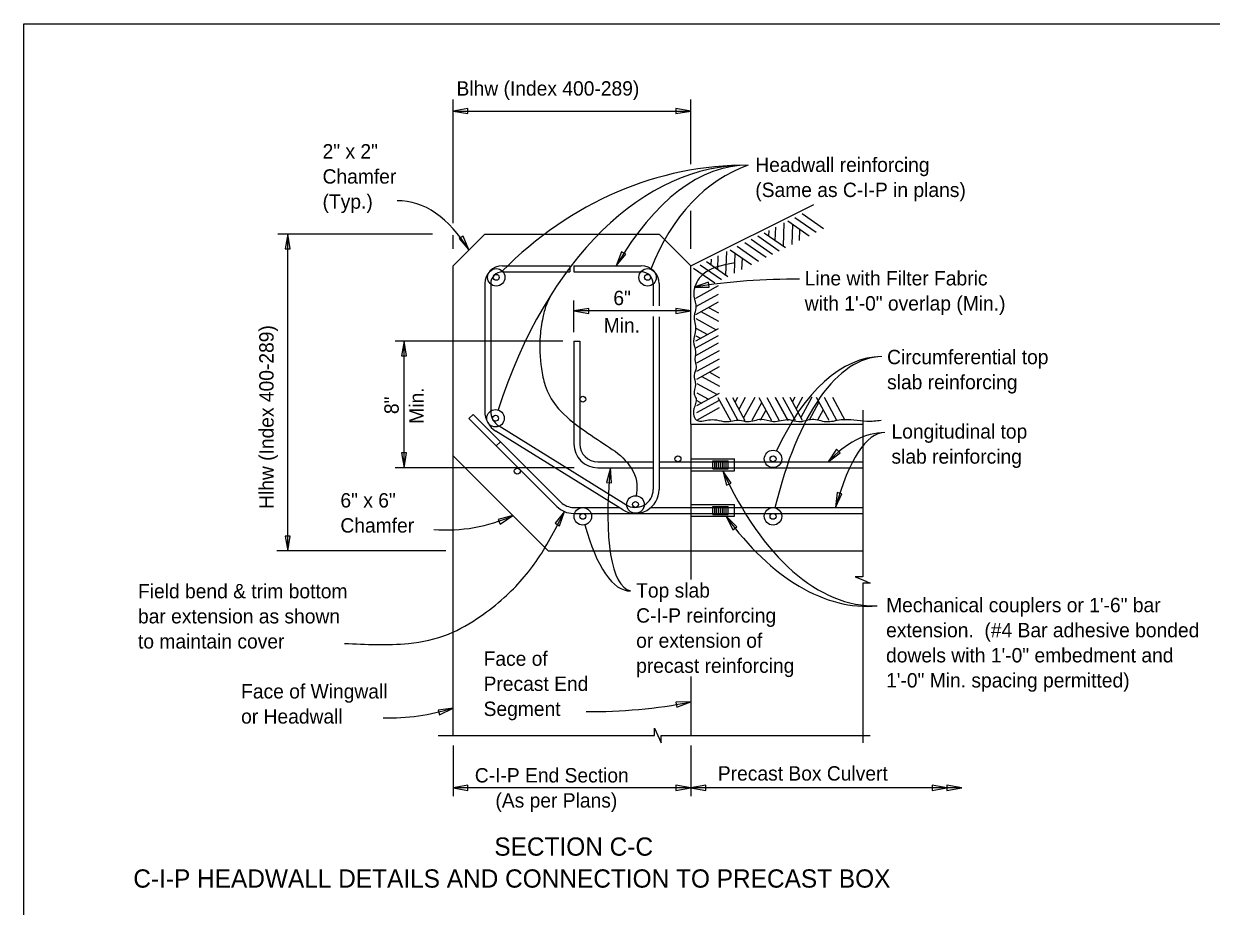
# Model space of a CAD drawing. Extents: x 0 to 15.4, y 0 to 9.7.
# Drawn here: x 0 to 6.24, y 5.1 to 9.74 of the extents above; entities that cross this region are included whole.
import ezdxf

# ---------------------------------------------------------------- set-up
doc = ezdxf.new("R2010")
doc.units = 0
for name, color, linetype in [('Dimension', 7, 'Continuous'), ('Miscellaneous', 7, 'Continuous'), ('Miscellaneous1', 7, 'Continuous'), ('Rebar', 7, 'Continuous'), ('SubStrConc', 7, 'Continuous'), ('TextStructures', 7, 'Continuous')]:
    doc.layers.add(name, color=color, linetype=linetype)

msp = doc.modelspace()

# ---------------------------------------------------------------- linework, layer by layer
at = {"layer": 'Dimension'}
for p, q in [((2.2567, 8.6893), (2.2567, 9.3394)), ((3.5067, 9), (3.5067, 9.3394)), ((2.2567, 9.2789), (3.5067, 9.2789)), ((3.5067, 8.5545), (3.5067, 8.7544)), ((2.1482, 8.6319), (1.3355, 8.6319)), ((1.3881, 6.9652), (1.3881, 8.6319)), ((2.2567, 8.5545), (2.2567, 8.6268)), ((2.8922, 8.1171), (2.8922, 8.2828)), ((3.5067, 8.2279), (2.8922, 8.2279)), ((2.8342, 8.0695), (1.953, 8.0695)), ((1.9994, 7.4028), (1.9994, 8.0695)), ((2.8933, 7.4028), (1.953, 7.4028)), ((2.2191, 6.9652), (1.3309, 6.9652)), ((2.2567, 5.9412), (2.2567, 5.6754)), ((3.5067, 5.9412), (3.5067, 5.6754)), ((3.5067, 5.7192), (2.2567, 5.7192)), ((4.931, 5.7192), (3.5067, 5.7192))]:
    msp.add_line(p, q, dxfattribs=at)
for points in [[(2.2567, 9.2789), (2.3348, 9.2657), (2.3348, 9.2921)], [(3.5067, 9.2789), (3.4286, 9.2921), (3.4286, 9.2657)], [(1.3881, 8.6319), (1.3748, 8.5538), (1.4013, 8.5538)], [(2.3401, 8.5486), (2.3107, 8.6221), (2.2881, 8.6083)], [(3.1144, 8.4652), (3.1649, 8.5263), (3.142, 8.5395)], [(3.5242, 8.3537), (3.6034, 8.3529), (3.5992, 8.379)], [(2.8922, 8.2279), (2.9703, 8.2147), (2.9703, 8.2412)], [(3.5067, 8.2279), (3.4286, 8.2412), (3.4286, 8.2147)], [(1.9993, 8.0695), (1.9861, 7.9914), (2.0126, 7.9914)], [(4.2289, 7.434), (4.2918, 7.4822), (4.2724, 7.5002)], [(1.9993, 7.4028), (2.0126, 7.4809), (1.9861, 7.4809)], [(3.0838, 7.4028), (3.0632, 7.3263), (3.0895, 7.3238)], [(3.6744, 7.3874), (3.6946, 7.3108), (3.7187, 7.3217)], [(4.2677, 7.1943), (4.3013, 7.266), (4.2758, 7.2731)], [(2.5709, 7.151), (2.4943, 7.131), (2.5051, 7.1069)], [(2.8426, 7.1726), (2.7928, 7.111), (2.8159, 7.0981)], [(3.6918, 7.1477), (3.727, 7.0767), (3.7484, 7.0923)], [(1.3881, 6.9652), (1.4013, 7.0433), (1.3748, 7.0433)], [(2.2567, 6.1391), (2.1782, 6.1282), (2.1862, 6.1029)], [(3.5067, 6.1713), (3.4275, 6.1691), (3.4326, 6.1431)], [(2.2567, 5.7192), (2.3348, 5.706), (2.3348, 5.7325)], [(3.5067, 5.7192), (3.4286, 5.7325), (3.4286, 5.706)], [(3.5067, 5.7192), (3.5848, 5.706), (3.5848, 5.7325)], [(4.853, 5.7192), (4.7749, 5.7325), (4.7749, 5.706)], [(4.931, 5.7192), (4.853, 5.7325), (4.853, 5.706)]]:
    msp.add_lwpolyline(points, close=True, dxfattribs=at)
for points in [[(4.4103, 7.7058), (4.4103, 6.83), (4.3715, 6.83), (4.4103, 6.8132), (4.449, 6.7963), (4.4103, 6.7963), (4.4103, 5.9557)], [(2.1788, 5.9944), (3.3166, 5.9944), (3.3166, 6.0332), (3.3335, 5.9944), (3.3504, 5.9557), (3.3504, 5.9944), (4.449, 5.9944)]]:
    msp.add_lwpolyline(points, dxfattribs=at)
for centre in [(2.4839, 8.4047), (3.2795, 8.4047), (2.4801, 7.6634), (3.939, 7.4496), (3.2159, 7.2099), (2.939, 7.1475), (3.939, 7.1475)]:
    msp.add_circle(centre, 0.0459, dxfattribs=at)
for centre, radius, start, end in [((4.0438, 5.0922), 3.3027, 89.39705, 99.05348), ((2.22, 7.93), 0.8544, 265.64331, 294.25209), ((1.9186, 7.2073), 1.1204, 268.54133, 287.56513), ((2.9908, 8.7724), 2.6517, 269.25675, 281.21871)]:
    msp.add_arc(centre, radius, start, end, dxfattribs=at)
for centre, major_axis, ratio, start_param, end_param in [((3.7845, 6.6328), (-0.0243, -2.3612), 0.617071, 3.141593, 4.246347), ((3.7916, 6.7521), (-0.0172, -2.2419), 0.865159, 3.141593, 3.868244), ((3.7834, 6.5654), (-0.0255, -2.4287), 0.452522, 3.141593, 3.818879), ((4.4723, 7.0644), (0.6635, -1.9296), 0.580134, 3.141593, 3.735964), ((1.984, 7.8602), (0.0202, -0.9471), 0.562458, 2.372304, 3.141593), ((4.5275, 6.3273), (0.0171, -1.6604), 0.402699, 3.141593, 4.160334), ((4.5275, 6.3273), (0.0171, -1.6604), 0.473544, 3.141593, 3.930463), ((4.5609, 5.8713), (0.0343, -1.7172), 0.430483, 3.141593, 3.560489), ((4.5609, 5.8713), (0.0343, -1.7172), 0.245056, 3.141593, 3.827956), ((3.4878, 7.9782), (0.2985, 1.223), 0.238216, 2.117736, 3.141593), ((4.4472, 8.7163), (-0.0394, 2.0403), 0.511198, 2.270212, 3.141593), ((4.2975, 8.9171), (-0.1891, 2.2412), 0.515902, 2.436127, 3.141593), ((3.1606, 7.5661), (-0.0288, 0.811), 0.337532, 2.166568, 3.141593)]:
    msp.add_ellipse(centre, major_axis=major_axis, ratio=ratio, start_param=start_param, end_param=end_param, dxfattribs=at)
for points in [[(2.7746, 8.3181), (2.7462, 8.2574), (2.7287, 8.1933), (2.7147, 8.0965), (2.7218, 7.9244), (2.7407, 7.8365), (2.7993, 7.7279), (2.9165, 7.6209), (3.0493, 7.5297), (3.1624, 7.4418), (3.2233, 7.316), (3.2191, 7.2557)], [(1.6858, 6.4793), (2.0233, 6.4793), (2.2331, 6.5283), (2.3999, 6.6212), (2.5253, 6.7198), (2.7032, 6.9244), (2.8426, 7.1726)]]:
    msp.add_spline(points, degree=3, dxfattribs=at)
at = {"layer": 'Miscellaneous'}
for p, q in [((3.5067, 8.4652), (4.1533, 8.7885)), ((4.0929, 8.7397), (4.2051, 8.6619)), ((3.9963, 8.6914), (3.9917, 8.5695)), ((4.0161, 8.7013), (4.1287, 8.6237)), ((4.041, 8.6842), (4.0373, 8.578)), ((4.0533, 8.7199), (4.1655, 8.6421)), ((3.8585, 8.6225), (3.9707, 8.5447)), ((3.8915, 8.639), (4.0037, 8.5612)), ((3.916, 8.6513), (3.915, 8.6228)), ((3.9518, 8.6692), (3.9492, 8.599)), ((4.0788, 8.6581), (4.0765, 8.5976)), ((3.7505, 8.5683), (3.8628, 8.4905)), ((3.7902, 8.5882), (3.9024, 8.5103)), ((3.8234, 8.605), (3.9356, 8.5271)), ((3.6132, 8.4997), (3.6122, 8.4712)), ((3.649, 8.5176), (3.6465, 8.4474)), ((3.6936, 8.5399), (3.689, 8.418)), ((3.7134, 8.5498), (3.8259, 8.4721)), ((3.7383, 8.5326), (3.7346, 8.4264)), ((3.7761, 8.5065), (3.7738, 8.446)), ((3.5207, 8.4534), (3.6329, 8.3756)), ((3.5558, 8.4709), (3.668, 8.3931)), ((3.5888, 8.4875), (3.701, 8.4096)), ((3.5323, 8.2955), (3.6521, 8.3611)), ((3.5323, 8.2512), (3.6521, 8.3168)), ((3.5323, 8.2097), (3.6521, 8.2756)), ((3.599, 8.2464), (3.6521, 8.2174)), ((3.5323, 8.1876), (3.6392, 8.1289)), ((3.5588, 8.2243), (3.6521, 8.1735)), ((3.5323, 8.1377), (3.5939, 8.1041)), ((3.5323, 8.0704), (3.6521, 8.1359)), ((3.5323, 8.0335), (3.6521, 8.099)), ((3.5323, 8.0977), (3.5573, 8.0841)), ((3.5323, 7.9943), (3.6521, 8.0598)), ((3.5376, 7.9549), (3.6574, 8.0205)), ((3.5376, 7.9106), (3.6574, 7.9762)), ((3.5376, 7.8691), (3.6574, 7.935)), ((3.5641, 7.8837), (3.6574, 7.8328)), ((3.6043, 7.9058), (3.6574, 7.8767)), ((3.5376, 7.8469), (3.6445, 7.7883)), ((3.5376, 7.7971), (3.5992, 7.7635)), ((3.5376, 7.7298), (3.6574, 7.7953)), ((3.5376, 7.6928), (3.6574, 7.7584)), ((3.5376, 7.7571), (3.5626, 7.7434)), ((3.6491, 7.7719), (3.7146, 7.6521)), ((3.6882, 7.7719), (3.7538, 7.6521)), ((3.7252, 7.7719), (3.7907, 7.6521)), ((3.7525, 7.7719), (3.7389, 7.7468)), ((3.7925, 7.7719), (3.7589, 7.7102)), ((3.8424, 7.7719), (3.7837, 7.6649)), ((3.8791, 7.7454), (3.8282, 7.6521)), ((3.8645, 7.7719), (3.9304, 7.6521)), ((3.906, 7.7719), (3.9716, 7.6521)), ((3.9503, 7.7719), (4.0159, 7.6521)), ((3.9504, 7.7739), (4.0159, 7.6541)), ((3.9895, 7.7739), (4.0551, 7.6541)), ((4.0265, 7.7739), (4.092, 7.6541)), ((4.0538, 7.7739), (4.0402, 7.7489)), ((4.0938, 7.7739), (4.0602, 7.7122)), ((4.1437, 7.7739), (4.085, 7.6669)), ((4.1804, 7.7474), (4.1296, 7.6541)), ((4.1658, 7.7739), (4.2317, 7.6541)), ((4.2073, 7.7739), (4.2729, 7.6541)), ((4.2516, 7.7739), (4.3172, 7.6541)), ((3.5376, 7.6536), (3.6574, 7.7192)), ((3.9012, 7.7051), (3.8721, 7.6521)), ((4.2025, 7.7072), (4.1735, 7.6541)), ((3.5067, 7.4494), (3.7355, 7.4494)), ((3.6226, 7.4393), (3.6626, 7.4393)), ((3.6226, 7.3975), (3.6226, 7.4393)), ((3.6326, 7.3975), (3.6326, 7.4393)), ((3.6426, 7.3975), (3.6426, 7.4393)), ((3.6526, 7.3975), (3.6526, 7.4393)), ((3.6626, 7.4393), (3.7026, 7.4393)), ((3.6626, 7.3975), (3.6626, 7.4393)), ((3.6726, 7.3975), (3.6726, 7.4393)), ((3.6826, 7.3975), (3.6826, 7.4393)), ((3.6926, 7.3975), (3.6926, 7.4393)), ((3.7026, 7.3975), (3.7026, 7.4393)), ((3.5067, 7.3874), (3.7355, 7.3874)), ((3.6226, 7.3975), (3.6626, 7.3975)), ((3.6626, 7.3975), (3.7026, 7.3975)), ((3.5067, 7.2097), (3.7355, 7.2097)), ((3.6226, 7.1996), (3.7026, 7.1996)), ((3.6226, 7.1578), (3.6226, 7.1996)), ((3.6326, 7.1578), (3.6326, 7.1996)), ((3.6426, 7.1578), (3.6426, 7.1996)), ((3.6526, 7.1578), (3.6526, 7.1996)), ((3.6626, 7.1578), (3.6626, 7.1996)), ((3.6726, 7.1578), (3.6726, 7.1996)), ((3.6826, 7.1578), (3.6826, 7.1996)), ((3.6926, 7.1578), (3.6926, 7.1996)), ((3.7026, 7.1578), (3.7026, 7.1996)), ((3.5067, 7.1477), (3.7355, 7.1477)), ((3.6226, 7.1578), (3.7026, 7.1578))]:
    msp.add_line(p, q, dxfattribs=at)
for points in [[(3.7355, 7.3874), (3.7355, 7.4494)], [(3.7355, 7.1477), (3.7355, 7.2097)]]:
    msp.add_lwpolyline(points, dxfattribs=at)
msp.add_spline([(3.7394, 8.4816), (3.5514, 8.4001), (3.5228, 8.3048), (3.533, 8.245), (3.5241, 8.2018), (3.5317, 8.1305), (3.5215, 8.0669), (3.5317, 8.0135), (3.5291, 7.9613), (3.5355, 7.9295), (3.5241, 7.8901), (3.5317, 7.8405), (3.5241, 7.7909), (3.5342, 7.7667), (3.5228, 7.7132), (3.5412, 7.6511), (3.5649, 7.6489), (3.5991, 7.6547), (3.6411, 7.6547), (3.6907, 7.6458), (3.7632, 7.6535), (3.8052, 7.6458), (3.8765, 7.6585), (3.9401, 7.6471), (4.024, 7.656), (4.0737, 7.6458), (4.1449, 7.6585), (4.2174, 7.6458), (4.2963, 7.656), (4.432, 7.6484), (4.5067, 7.6527)], degree=3, dxfattribs=at)
at = {"layer": 'Miscellaneous1'}
msp.add_lwpolyline([(0, 9.7387), (15.4, 9.7387), (15.4, 0), (0, 0)], close=True, dxfattribs=at)
at = {"layer": 'Rebar'}
for p, q in [((2.5171, 8.4652), (2.8713, 8.4652)), ((2.5171, 8.434), (2.8713, 8.434)), ((2.8713, 8.4652), (2.8713, 8.434)), ((2.8921, 8.4652), (2.8921, 8.434)), ((2.8921, 8.4652), (3.2463, 8.4652)), ((2.8921, 8.434), (3.2463, 8.434)), ((2.4234, 8.3715), (2.4234, 7.7015)), ((2.4546, 8.3715), (2.4546, 7.7015)), ((3.3088, 8.3715), (3.3088, 8.2542)), ((3.34, 8.3715), (3.34, 8.2542)), ((3.3088, 8.1983), (3.3088, 7.2881)), ((3.34, 8.1976), (3.34, 7.2881)), ((2.8922, 8.0695), (2.8922, 7.5278)), ((2.8922, 8.0695), (2.9234, 8.0695)), ((2.9234, 8.0695), (2.9234, 7.5278)), ((2.34, 7.6618), (2.3621, 7.6838)), ((2.5061, 7.5398), (2.3621, 7.6838)), ((2.484, 7.5177), (2.34, 7.6618)), ((3.1656, 7.2084), (2.499, 7.6218)), ((3.1491, 7.1819), (2.4825, 7.5952)), ((2.484, 7.5177), (2.5061, 7.5398)), ((2.8021, 7.1997), (2.484, 7.5177)), ((2.8241, 7.2218), (2.5061, 7.5398)), ((3.0172, 7.434), (3.3088, 7.434)), ((3.34, 7.434), (4.4103, 7.434)), ((3.0172, 7.4028), (3.3088, 7.4028)), ((3.34, 7.4028), (4.4103, 7.4028)), ((3.3575, 7.4028), (3.5276, 7.4028)), ((2.8904, 7.1943), (3.1291, 7.1943)), ((3.2976, 7.1943), (4.4103, 7.1943)), ((2.8904, 7.1631), (4.4103, 7.1631))]:
    msp.add_line(p, q, dxfattribs=at)
for centre in [(2.4839, 8.4047), (3.2795, 8.4047), (2.939, 7.7635), (2.4801, 7.6634), (3.439, 7.4496), (3.939, 7.4496), (2.5944, 7.3853), (3.2159, 7.2099), (2.939, 7.1475), (3.939, 7.1475)]:
    msp.add_circle(centre, 0.0156, dxfattribs=at)
for centre, radius, start, end in [((2.5171, 8.3715), 0.0937, 90.00037, 179.99954), ((2.5171, 8.3715), 0.0625, 90, 180), ((3.2463, 8.3715), 0.0937, 0.00037, 90.00037), ((3.2463, 8.3715), 0.0625, 0, 90), ((2.5484, 7.7015), 0.125, 180, 238.19596), ((2.5484, 7.7015), 0.0938, 180, 238.19632), ((3.0172, 7.5278), 0.125, 180, 269.99247), ((3.0172, 7.5278), 0.0938, 180, 270), ((3.215, 7.2881), 0.125, 238.19608, 0), ((3.215, 7.2881), 0.0938, 238.19609, 0), ((2.8904, 7.2881), 0.125, 225, 269.99247), ((2.8904, 7.2881), 0.0938, 225, 270)]:
    msp.add_arc(centre, radius, start, end, dxfattribs=at)
at = {"layer": 'SubStrConc'}
for p, q in [((2.4234, 8.6319), (2.2567, 8.4652)), ((2.4234, 8.6319), (3.34, 8.6319)), ((3.5067, 8.4652), (3.34, 8.6319)), ((2.2567, 7.4652), (2.2567, 8.4652)), ((3.5067, 7.6319), (3.5067, 8.4652)), ((3.5067, 7.6319), (4.4103, 7.6319)), ((3.5067, 7.6319), (3.5067, 6.8154)), ((2.2567, 5.9944), (2.2567, 7.4652)), ((2.7567, 6.9652), (2.2567, 7.4652)), ((2.7567, 6.9652), (4.4103, 6.9652)), ((3.5067, 6.3045), (3.5067, 5.9944))]:
    msp.add_line(p, q, dxfattribs=at)
at = {"layer": 'TextStructures'}
msp.add_lwpolyline([(0, 9.7387), (15.4, 9.7387), (15.4, 0), (0, 0)], close=True, dxfattribs=at)

# ---------------------------------------------------------------- texts
for s, height, p in [('Blhw (Index 400-289)', 0.0756, (2.275, 9.3607)), ('2" x 2" ', 0.0756, (1.5709, 9.0297)), ('Headwall reinforcing', 0.0756, (3.8457, 8.9591)), ('Chamfer', 0.0756, (1.5709, 8.8977)), ('(Same as C-I-P in plans)', 0.0756, (3.8457, 8.8271)), ('(Typ.)', 0.0756, (1.5709, 8.7657)), ('Line with Filter Fabric', 0.0756, (4.1057, 8.3621)), ('6"', 0.0756, (3.0995, 8.2585)), ('with 1\'-0" overlap (Min.)', 0.0756, (4.1057, 8.2301)), ('Min.', 0.0756, (3.0487, 8.1145)), ('Circumferential top', 0.0756, (4.5385, 7.9478)), ('slab reinforcing', 0.0756, (4.5385, 7.8158)), ('Longitudinal top', 0.0756, (4.5616, 7.5565)), ('slab reinforcing', 0.0756, (4.5616, 7.4245)), ('6" x 6"', 0.0756, (1.6647, 7.1939)), ('Chamfer', 0.0756, (1.6647, 7.0619)), ('Field bend & trim bottom', 0.0756, (0.6006, 6.7162)), ('Top slab', 0.0756, (3.2194, 6.7202)), ('Mechanical couplers or 1\'-6" bar', 0.0756, (4.5333, 6.6431)), ('bar extension as shown', 0.0756, (0.6006, 6.5842)), ('C-I-P reinforcing', 0.0756, (3.2194, 6.5882)), ('extension.  (#4 Bar adhesive bonded', 0.0756, (4.5333, 6.5111)), ('to maintain cover', 0.0756, (0.6006, 6.4522)), ('or extension of', 0.0756, (3.2194, 6.4562)), ('Face of', 0.0756, (2.4174, 6.3612)), ('dowels with 1\'-0" embedment and', 0.0756, (4.5333, 6.3791)), ('precast reinforcing', 0.0756, (3.2194, 6.3242)), ('Precast End', 0.0756, (2.4174, 6.2292)), ('1\'-0" Min. spacing permitted)', 0.0756, (4.5333, 6.2471)), ('Face of Wingwall', 0.0756, (1.1427, 6.1893)), ('or Headwall', 0.0756, (1.1427, 6.0573)), ('Segment', 0.0756, (2.4174, 6.0972)), ('C-I-P End Section', 0.0756, (2.3712, 5.7474)), ('Precast Box Culvert', 0.0756, (3.6489, 5.7574)), ('(As per Plans)', 0.0756, (2.4796, 5.6154)), ('SECTION C-C', 0.096, (2.4738, 5.3623)), ('C-I-P HEADWALL DETAILS AND CONNECTION TO PRECAST BOX', 0.096, (0.5759, 5.1943))]:
    msp.add_text(s, height=height, dxfattribs=at).set_placement(p)
for s, p in [('Hlhw (Index 400-289)', (1.3136, 7.1865)), ('Min.', (2.1032, 7.6345)), ('8"', (1.9712, 7.6853))]:
    msp.add_text(s, height=0.0756, rotation=90, dxfattribs=at).set_placement(p)

doc.saveas('drawing.dxf')
